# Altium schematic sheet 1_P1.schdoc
size 307 x 218 mm; Symbol: Drawing-Symbol_A4; Device: Drawing-Symbol_A4; @Project Name: odin-core; @Page Count: 1; @Update Date: 2026-05-22; @Create Date: 2026-05-22; @Schematic Name: Schematic1; @Page No: 1; @Page Name: P1; Company: HeyCallMeK; Version: V1.0; Page Size: A4; @Create Time: 13:18:10; @Update Time: 18:48:10; Width: 1170; Height: 825; Region Start: 1; X Region Count: 6; Y Region Count: 4; Blade Width: 10; Title Block Position: 3; @Board Name: Board1
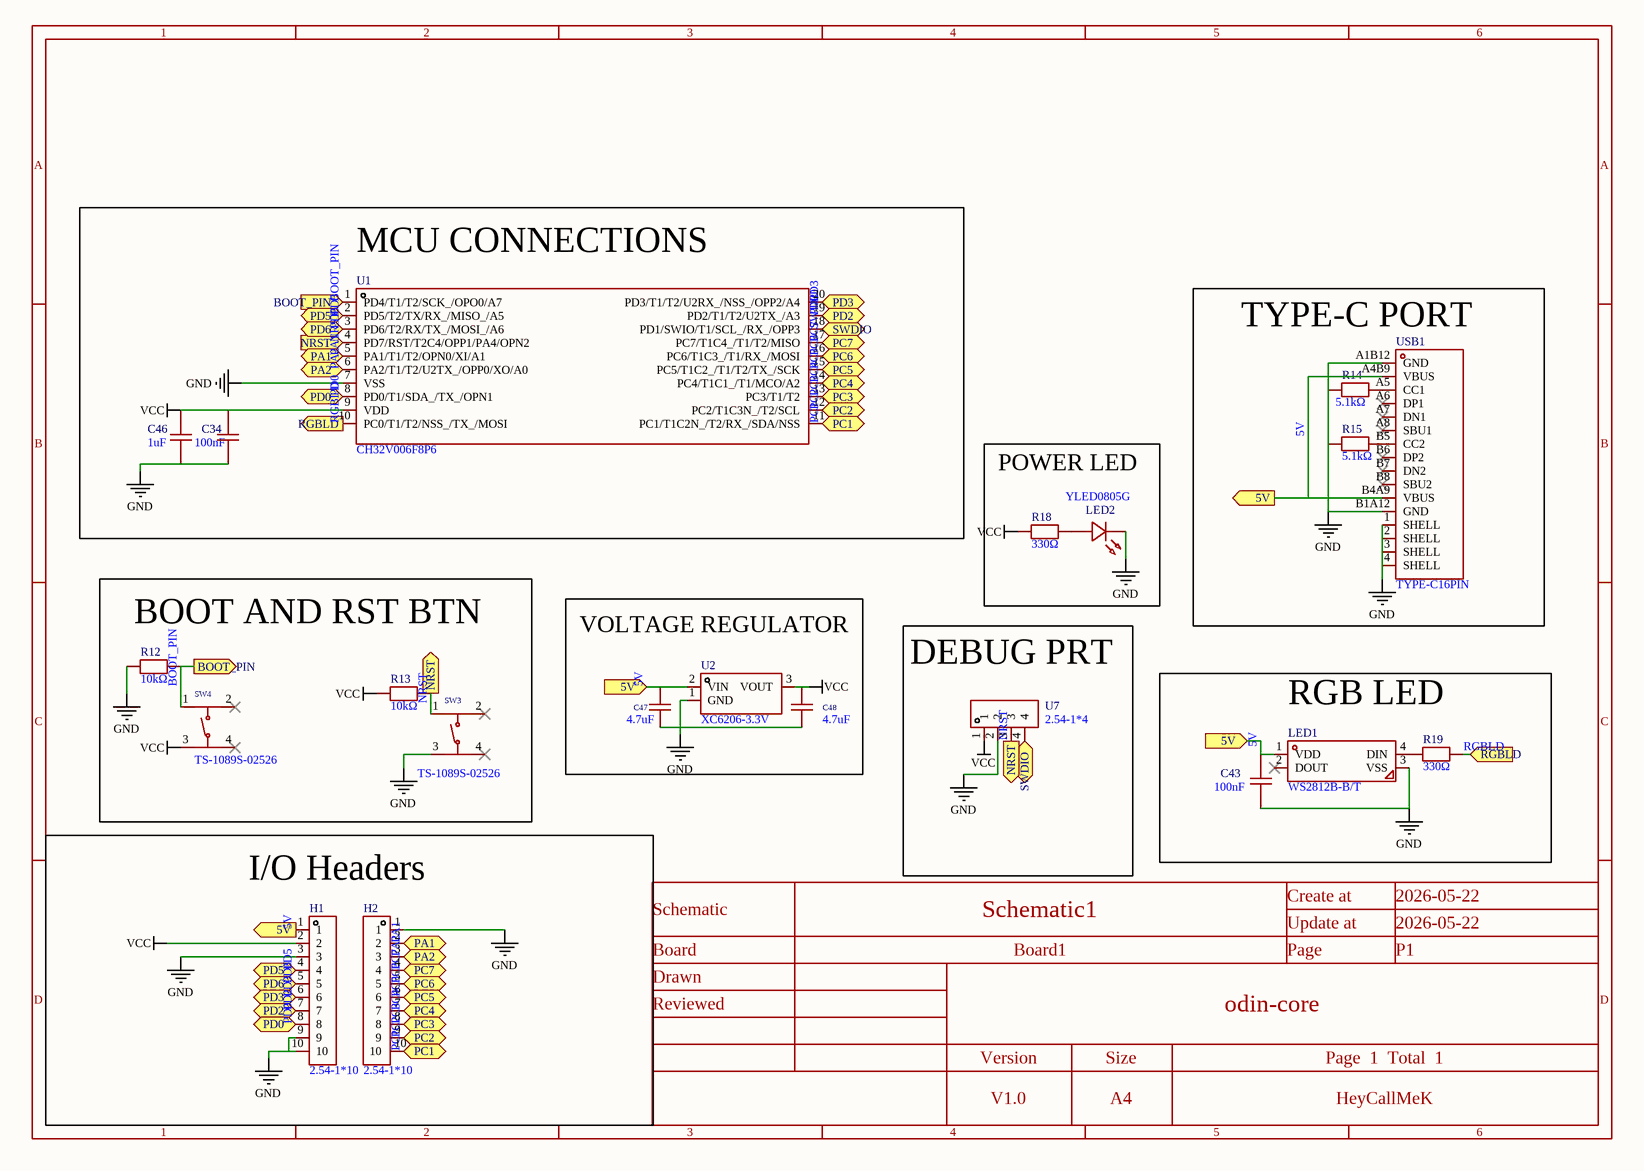
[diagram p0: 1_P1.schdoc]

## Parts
C34  100nF  [C0603]
C43  100nF  [C0603]
C46  1uF  [C0603]
C47  4.7uF  [C0603]
C48  4.7uF  [C0603]
H1  2.54-1*10  [HDR-TH_10P-P2.54-V-M]
H2  2.54-1*10  [HDR-TH_10P-P2.54-V-M]
LED1  WS2812B-B/T  [LED-SMD_4P-L5.0-W5.0-TL_WS2812B-B]
LED2  YLED0805G  [LED0805-FD-GREEN]
R12  10kΩ  [R0603]
R13  10kΩ  [R0603]
R14  5.1kΩ  [R0603]
R15  5.1kΩ  [R0603]
R18  330Ω  [R0603]
R19  330Ω  [R0603]
SW3  TS-1089S-02526  [SW-SMD_4P-L4.2-W3.3-P2.15-LS5.1]
SW4  TS-1089S-02526  [SW-SMD_4P-L4.2-W3.3-P2.15-LS5.1]
U1  CH32V006F8P6  [TSSOP-20_L6.5-W4.4-P0.65-LS6.4-BL]
U2  XC6206-3.3V  [SOT-89-3_L4.3-W2.3-P1.50-LS4.3-BR]
U7  2.54-1*4  [HDR-TH_4P-P2.54-V-M-1]
USB1  TYPE-C16PIN  [USB-C-SMD_TYPE-C16PIN]

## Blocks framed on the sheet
MCU CONNECTIONS: C34 C46 U1
TYPE-C PORT: R14 R15 USB1
POWER LED: LED2 R18
BOOT AND RST BTN: R12 R13 SW3 SW4
VOLTAGE REGULATOR: C47 C48 U2
DEBUG PRT: U7
RGB LED: C43 LED1 R19
I/O Headers: H1 H2

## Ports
5V (in), 5V (out), BOOT_PIN (in), BOOT_PIN (out), NRST (in), NRST (out), PA1 (bidir), PA2 (bidir), PC1 (bidir), PC2 (bidir), PC3 (bidir), PC4 (bidir), PC5 (bidir), PC6 (bidir), PC7 (bidir), PD0 (bidir), PD2 (bidir), PD3 (bidir), PD5 (bidir), PD6 (bidir), RGBLD (in), RGBLD (out), SWDIO (bidir)

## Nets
GND: C34.1 C43.1 C46.2 C47.2 C48.2 H1.3 H1.9 H1.10 H2.1 LED1.3(VSS) LED2.2(K) R12.1 R14.1 R15.1 SW3.3 U1.7(VSS) U2.1(GND) U7.2 USB1.1(SHELL) USB1.2(SHELL) USB1.3(SHELL) USB1.4(SHELL) USB1.A1B12(GND) USB1.B1A12(GND)
VCC: C34.2 C46.1 C48.1 H1.2 R13.1 R18.1 SW4.3 U1.9(VDD) U2.3(VOUT) U7.1
5V: C43.2 C47.1 H1.1 LED1.1(VDD) U2.2(VIN) USB1.A4B9(VBUS) USB1.B4A9(VBUS) ; port 5V
BOOT_PIN: R12.2 SW4.1 U1.1(PD4/T1/T2/SCK_/OPO0/A7) ; port BOOT_PIN
NRST: R13.2 SW3.1 U1.4(PD7/RST/T2C4/OPP1/PA4/OPN2) U7.3 ; port NRST
PA1: H2.2 U1.5(PA1/T1/T2/OPN0/XI/A1) ; port PA1
PA2: H2.3 U1.6(PA2/T1/T2/U2TX_/OPP0/XO/A0) ; port PA2
PC1: H2.10 U1.11(PC1/T1C2N_/T2/RX_/SDA/NSS) ; port PC1
PC2: H2.9 U1.12(PC2/T1C3N_/T2/SCL) ; port PC2
PC3: H2.8 U1.13(PC3/T1/T2) ; port PC3
PC4: H2.7 U1.14(PC4/T1C1_/T1/MCO/A2) ; port PC4
PC5: H2.6 U1.15(PC5/T1C2_/T1/T2/TX_/SCK) ; port PC5
PC6: H2.5 U1.16(PC6/T1C3_/T1/RX_/MOSI) ; port PC6
PC7: H2.4 U1.17(PC7/T1C4_/T1/T2/MISO) ; port PC7
PD0: H1.8 U1.8(PD0/T1/SDA_/TX_/OPN1) ; port PD0
PD2: H1.7 U1.19(PD2/T1/T2/U2TX_/A3) ; port PD2
PD3: H1.6 U1.20(PD3/T1/T2/U2RX_/NSS_/OPP2/A4) ; port PD3
PD5: H1.4 U1.2(PD5/T2/TX/RX_/MISO_/A5) ; port PD5
PD6: H1.5 U1.3(PD6/T2/RX/TX_/MOSI_/A6) ; port PD6
RGBLD: R19.2 U1.10(PC0/T1/T2/NSS_/TX_/MOSI) ; port RGBLD
SWDIO: U1.18(PD1/SWIO/T1/SCL_/RX_/OPP3) U7.4 ; port SWDIO
NetLED1_4: LED1.4(DIN) R19.1
NetLED2_1: LED2.1(A) R18.2
NetR14_2: R14.2 USB1.A5(CC1)
NetR15_2: R15.2 USB1.B5(CC2)

Not connected (* = marked no-connect by the designer): LED1 2(DOUT)*; SW3 2* 4*; SW4 2* 4*; USB1 A6(DP1)* A7(DN1)* A8(SBU1)* B6(DP2)* B7(DN2)* B8(SBU2)*

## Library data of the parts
C34 C43 = FCC0603B104K500CT: Manufacturer: FOJAN(富捷); Add into BOM: yes; Tolerance: ±10%; Voltage Rating: 50V; Temperature Coefficient: X7R
C46 = CGA0603X5R105K500JT: Manufacturer: HRE(芯声); Add into BOM: yes; Tolerance: ±10%; Voltage Rating: 50V; Temperature Coefficient: X5R
C47 C48 = CL10A475KP8NNNC: Manufacturer: SAMSUNG(三星); Add into BOM: yes; Tolerance: ±10%; Voltage Rating: 10V; Temperature Coefficient: X5R
H1 H2 = 2.54-1*10: Manufacturer: ZHOURI(洲日); Add into BOM: yes; Pin Structure: 1x10P; Pitch: 2.54mm; Circluar Pins/Square Pins: Pin Header; Current Rating: 2.5A
LED1 = WS2812B-B/T: Manufacturer: worldsemi; Symbol: WS2812B-B/W; Add into BOM: yes; Wavelength: 520nm；471nm；621nm; Luminous Intensity: R:300mcd~500mcd；B:200mcd~300mcd；G:600mcd~1000mcd; Fixed-Frequency Pwm Mode: 2kHz; Data Transmission Rate: 800Kbit/s; Quiescent Current: 0.6mA; Peak Wavelength: G:520nm；R:621nm；B:471nm
LED2 = YLED0805G: Manufacturer: YONGYUTAI(永裕泰); Add into BOM: yes; Lamp Holder Type: 2mm x 1.25mm square LED; Illumination Color: Emerald Green; Voltage - Forward(Vf): 2.4V~3.1V; Power(Watts): 70mW; Forward Current: 20mA; Wavelength - Dominant: 516nm~534nm; Peak Wavelength: 525nm; Diode Configuration: Discrete Diode; Lens Color: Water Clear; Luminous Intensity: 430mcd; Viewing Angle: 120°
R12 R13 = FRC0603J103 TS: Manufacturer: FOJAN(富捷); Add into BOM: yes; Tolerance: ±5%; Power(Watts): 100mW; Voltage-Supply(Max): 75V; Temperature Coefficient: ±100ppm/℃
R14 R15 = FRC0603F5101TS: Manufacturer: FOJAN(富捷); Add into BOM: yes; Tolerance: ±1%; Power(Watts): 100mW; Voltage-Supply(Max): 75V; Temperature Coefficient: ±100ppm/℃
R18 R19 = FRC0603J331 TS: Manufacturer: FOJAN(富捷); Add into BOM: yes; Tolerance: ±5%; Power(Watts): 100mW; Voltage-Supply(Max): 75V; Temperature Coefficient: ±100ppm/℃
SW3 SW4 = TS-1089S-02526: Manufacturer: XUNPU(讯普); Add into BOM: yes; Circuit: SPST; Actuator Style: Oval button; Switch Length: 4.2mm; Switch Width: 3.25mm; Switch Height: 2.5mm; Contact Current: 50mA; Voltage Rating (DC): 12V
U1 = CH32V006F8P6_C52753342: Manufacturer: WCH(南京沁恒); Add into BOM: yes
U2 = XC6206-3.3V_C7603199: Manufacturer: YONGYUTAI(永裕泰); Add into BOM: yes
U7 = 2.54-1*4: Manufacturer: ZHOURI(洲日); Add into BOM: yes; Pin Structure: 1x4P; Pitch: 2.54mm; Circluar Pins/Square Pins: Pin Header; Current Rating: 2.5A
USB1 = TYPE-C16PIN: Manufacturer: SHOU HAN(首韩); Add into BOM: yes; Connector Type: Type-C; Gender: Female; Number of Contacts: 16P; Number of Ports: 1; Current Rating-Power: 3A; Voltage Rating: 30V; Connect-Disconnect Life: 10,000 Cycles; Detection color: Black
